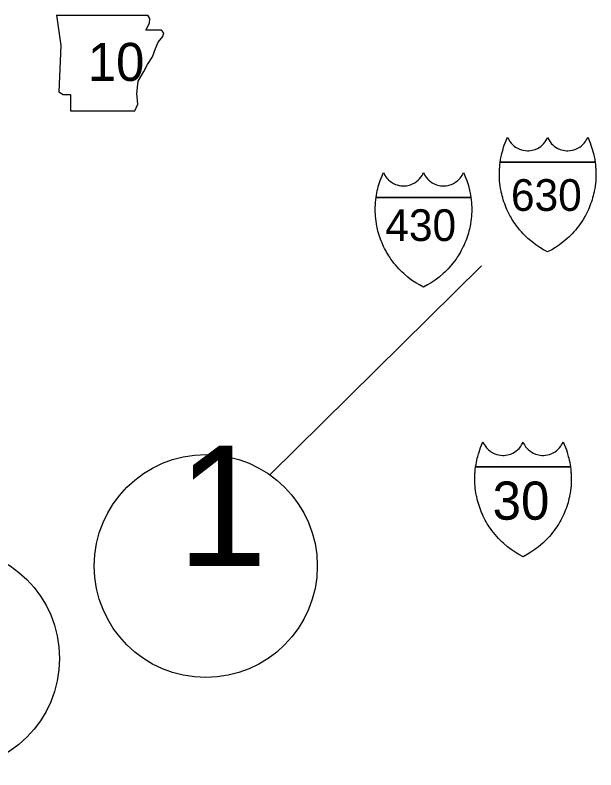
# Model space of a CAD drawing. Extents: x -819161 to 80911, y -6604 to 768454.
# Drawn here: x 43414 to 44380, y -5063 to -3807 of the extents above; entities that cross this region are included whole.
import ezdxf

# ---------------------------------------------------------------- set-up
doc = ezdxf.new("R2010")
doc.units = 0
for name, color, linetype in [('21', 7, 'Continuous'), ('23', 7, 'Continuous'), ('DSN_DRFT_Common-Line', 7, 'Continuous'), ('Level 23', 7, 'Continuous')]:
    doc.layers.add(name, color=color, linetype=linetype)

msp = doc.modelspace()

# ---------------------------------------------------------------- linework, layer by layer
at = {"layer": '21'}
for p, q in [((43482.9, -3807.3), (43490.5, -3858)), ((43638.5, -3813.2), (43635, -3807.3)), ((43637.7, -3820.8), (43638.5, -3813.2)), ((43631.8, -3832.6), (43637.7, -3820.8)), ((43658, -3832.6), (43631.8, -3832.6)), ((43661.4, -3836.9), (43658, -3832.6)), ((43659.7, -3842.8), (43661.4, -3836.9)), ((43647.9, -3863.1), (43652.1, -3852.1)), ((43652.1, -3852.1), (43659.7, -3842.8)), ((43490.5, -3858), (43487.1, -3935)), ((43642.8, -3876.6), (43647.9, -3863.1)), ((43634.3, -3889.3), (43642.8, -3876.6)), ((43628.4, -3901.2), (43634.3, -3889.3)), ((43619.1, -3917.2), (43628.4, -3901.2)), ((43616.6, -3937.5), (43619.1, -3917.2)), ((43487.1, -3935), (43493.9, -3939.2)), ((43493.9, -3939.2), (43506.6, -3939.2)), ((43506.6, -3939.2), (43506.6, -3966.3)), ((43618.2, -3955.3), (43616.6, -3937.5)), ((43613.2, -3966.3), (43618.2, -3955.3)), ((43506.6, -3966.3), (43613.2, -3966.3))]:
    msp.add_line(p, q, dxfattribs=at)
msp.add_lwpolyline([(43482.9, -3807.3), (43635, -3807.3)], dxfattribs=at)
at = {"layer": '23'}
for points in [[(44221.3, -4051.9), (44221.9, -4048.2), (44222.5, -4044.8), (44223.4, -4040.5), (44224, -4037.7), (44224.9, -4034.4), (44226, -4030.5), (44227, -4027.2), (44228.1, -4023.9), (44229.6, -4019.7), (44231.2, -4015.8), (44232.5, -4012.8), (44233.5, -4010.5), (44234.7, -4013), (44236, -4015.5), (44237.5, -4017.7), (44239.4, -4020.2), (44240.9, -4021.9), (44242.8, -4023.7), (44244.7, -4025.3), (44246.8, -4026.8), (44250, -4028.7), (44253.4, -4030.3), (44256.4, -4031.4), (44259.4, -4032.1), (44262.7, -4032.7), (44266.4, -4032.9), (44268.9, -4032.9), (44271.7, -4032.6), (44274.2, -4032.2), (44276.9, -4031.5), (44279.6, -4030.6), (44283.3, -4029), (44285.8, -4027.6), (44288.7, -4025.6), (44291.5, -4023.2), (44293.5, -4021.2), (44295.9, -4018.3), (44297.8, -4015.4), (44298.9, -4013.4), (44300.2, -4010.8)], [(44300.2, -4010.8), (44301.4, -4013.4), (44302.6, -4015.4), (44304.5, -4018.3), (44306.8, -4021.2), (44308.9, -4023.2), (44311.7, -4025.6), (44314.6, -4027.6), (44317.1, -4029), (44320.8, -4030.6), (44323.5, -4031.5), (44326.2, -4032.2), (44328.7, -4032.6), (44331.5, -4032.9), (44334, -4032.9), (44337.7, -4032.7), (44340.9, -4032.1), (44343.9, -4031.4), (44347, -4030.3), (44350.3, -4028.7), (44353.6, -4026.8), (44355.7, -4025.3), (44357.6, -4023.7), (44359.4, -4021.9), (44360.9, -4020.2), (44362.9, -4017.7), (44364.3, -4015.5), (44365.7, -4013), (44366.8, -4010.5), (44367.9, -4012.8), (44369.2, -4015.8), (44370.7, -4019.7), (44372.3, -4023.9), (44373.4, -4027.2), (44374.4, -4030.5), (44375.5, -4034.4), (44376.3, -4037.7), (44377, -4040.5), (44377.9, -4044.8), (44378.5, -4048.2), (44379, -4051.9)], [(44300.2, -4201.3), (44293.3, -4197.6), (44287.2, -4194), (44280.5, -4189.5), (44274.3, -4184.7), (44267.4, -4178.9), (44264.9, -4176.5), (44262, -4173.7), (44259.3, -4170.9), (44256.4, -4167.7), (44253.5, -4164.4), (44251.1, -4161.4), (44248.5, -4158), (44246.1, -4154.7), (44244.1, -4151.7), (44242.2, -4148.9), (44240.8, -4146.5), (44238.8, -4143.1), (44237.2, -4140.4), (44235.6, -4137.2), (44233.9, -4133.8), (44232.5, -4130.7), (44231.2, -4127.8), (44229.8, -4124.4), (44228.7, -4121.3), (44227.5, -4118.1), (44226.4, -4114.7), (44225.4, -4111.3), (44224.5, -4108), (44223.7, -4104.8), (44223.1, -4102), (44222.6, -4100), (44221.9, -4096), (44221.1, -4091.3), (44220.7, -4087.5), (44220.3, -4083.4), (44220.1, -4080.1), (44219.9, -4075.9), (44219.9, -4072), (44220, -4067.7), (44220.1, -4064.8), (44220.3, -4062.2), (44220.4, -4060.6), (44220.8, -4056.3), (44221.3, -4051.9)], [(44379, -4051.9), (44221.3, -4051.9)], [(44221.3, -4051.9), (44379, -4051.9)], [(44379, -4051.9), (44379.6, -4056.3), (44380, -4060.6), (44380.1, -4062.2), (44380.3, -4064.8), (44380.4, -4067.7), (44380.5, -4072), (44380.4, -4075.9), (44380.3, -4080.1), (44380.1, -4083.4), (44379.7, -4087.5), (44379.2, -4091.3), (44378.5, -4096), (44377.7, -4100), (44377.3, -4102), (44376.7, -4104.8), (44375.9, -4108), (44375, -4111.3), (44374, -4114.7), (44372.9, -4118.1), (44371.7, -4121.3), (44370.5, -4124.4), (44369.2, -4127.8), (44367.9, -4130.7), (44366.4, -4133.8), (44364.8, -4137.2), (44363.1, -4140.4), (44361.6, -4143.1), (44359.6, -4146.5), (44358.1, -4148.9), (44356.3, -4151.7), (44354.3, -4154.7), (44351.9, -4158), (44349.3, -4161.4), (44346.9, -4164.4), (44344, -4167.7), (44341.1, -4170.9), (44338.4, -4173.7), (44335.5, -4176.5), (44332.9, -4178.9), (44326.1, -4184.7), (44319.9, -4189.5), (44313.2, -4194), (44307.1, -4197.6), (44300.2, -4201.3)], [(44014.8, -4110.5), (44015.3, -4106.7), (44015.9, -4103.4), (44016.8, -4099.1), (44017.5, -4096.3), (44018.3, -4092.9), (44019.4, -4089), (44020.4, -4085.8), (44021.5, -4082.4), (44023, -4078.3), (44024.6, -4074.4), (44025.9, -4071.4), (44027, -4069), (44028.1, -4071.6), (44029.5, -4074), (44030.9, -4076.2), (44032.8, -4078.7), (44034.4, -4080.4), (44036.2, -4082.2), (44038.1, -4083.8), (44040.2, -4085.3), (44043.5, -4087.3), (44046.8, -4088.8), (44049.9, -4089.9), (44052.9, -4090.7), (44056.1, -4091.2), (44059.8, -4091.5), (44062.3, -4091.4), (44065.1, -4091.1), (44067.6, -4090.7), (44070.3, -4090), (44073, -4089.1), (44076.7, -4087.5), (44079.2, -4086.1), (44082.1, -4084.1), (44084.9, -4081.8), (44087, -4079.7), (44089.3, -4076.9), (44091.2, -4074), (44092.4, -4072), (44093.6, -4069.3)], [(44093.6, -4069.3), (44094.9, -4072), (44096, -4074), (44097.9, -4076.9), (44100.2, -4079.7), (44102.3, -4081.8), (44105.1, -4084.1), (44108, -4086.1), (44110.5, -4087.5), (44114.2, -4089.1), (44116.9, -4090), (44119.6, -4090.7), (44122.1, -4091.1), (44124.9, -4091.4), (44127.4, -4091.5), (44131.1, -4091.2), (44134.4, -4090.7), (44137.4, -4089.9), (44140.4, -4088.8), (44143.8, -4087.3), (44147, -4085.3), (44149.1, -4083.8), (44151, -4082.2), (44152.9, -4080.4), (44154.4, -4078.7), (44156.3, -4076.2), (44157.8, -4074), (44159.1, -4071.6), (44160.3, -4069), (44161.3, -4071.4), (44162.6, -4074.4), (44164.2, -4078.3), (44165.7, -4082.4), (44166.8, -4085.8), (44167.8, -4089), (44168.9, -4092.9), (44169.8, -4096.3), (44170.4, -4099.1), (44171.3, -4103.4), (44171.9, -4106.7), (44172.5, -4110.5)], [(44093.6, -4259.9), (44086.7, -4256.2), (44080.6, -4252.5), (44073.9, -4248), (44067.7, -4243.3), (44060.9, -4237.4), (44058.3, -4235.1), (44055.4, -4232.2), (44052.7, -4229.5), (44049.8, -4226.3), (44046.9, -4222.9), (44044.5, -4219.9), (44041.9, -4216.5), (44039.5, -4213.3), (44037.5, -4210.2), (44035.7, -4207.5), (44034.2, -4205.1), (44032.2, -4201.7), (44030.7, -4198.9), (44029, -4195.7), (44027.3, -4192.4), (44025.9, -4189.3), (44024.6, -4186.3), (44023.3, -4183), (44022.1, -4179.9), (44020.9, -4176.6), (44019.8, -4173.3), (44018.8, -4169.8), (44017.9, -4166.5), (44017.1, -4163.4), (44016.5, -4160.6), (44016, -4158.5), (44015.3, -4154.5), (44014.6, -4149.9), (44014.1, -4146), (44013.7, -4141.9), (44013.5, -4138.6), (44013.4, -4134.5), (44013.3, -4130.6), (44013.4, -4126.2), (44013.5, -4123.4), (44013.7, -4120.7), (44013.8, -4119.1), (44014.2, -4114.8), (44014.8, -4110.5)], [(44172.5, -4110.5), (44014.8, -4110.5)], [(44014.8, -4110.5), (44172.5, -4110.5)], [(44172.5, -4110.5), (44173, -4114.8), (44173.4, -4119.1), (44173.5, -4120.7), (44173.7, -4123.4), (44173.8, -4126.2), (44173.9, -4130.6), (44173.9, -4134.5), (44173.7, -4138.6), (44173.5, -4141.9), (44173.1, -4146), (44172.6, -4149.9), (44171.9, -4154.5), (44171.2, -4158.5), (44170.7, -4160.6), (44170.1, -4163.4), (44169.3, -4166.5), (44168.4, -4169.8), (44167.4, -4173.3), (44166.3, -4176.6), (44165.1, -4179.9), (44164, -4183), (44162.6, -4186.3), (44161.3, -4189.3), (44159.9, -4192.4), (44158.2, -4195.7), (44156.5, -4198.9), (44155, -4201.7), (44153, -4205.1), (44151.5, -4207.5), (44149.7, -4210.2), (44147.7, -4213.3), (44145.3, -4216.5), (44142.7, -4219.9), (44140.3, -4222.9), (44137.4, -4226.3), (44134.5, -4229.5), (44131.8, -4232.2), (44128.9, -4235.1), (44126.4, -4237.4), (44119.5, -4243.3), (44113.3, -4248), (44106.6, -4252.5), (44100.5, -4256.2), (44093.6, -4259.9)], [(44180.4, -4558.8), (44181, -4555), (44181.6, -4551.7), (44182.4, -4547.4), (44183.1, -4544.6), (44183.9, -4541.3), (44185, -4537.3), (44186, -4534.1), (44187.2, -4530.7), (44188.7, -4526.6), (44190.2, -4522.7), (44191.5, -4519.7), (44192.6, -4517.3), (44193.7, -4519.9), (44195.1, -4522.3), (44196.6, -4524.5), (44198.5, -4527), (44200, -4528.7), (44201.9, -4530.5), (44203.8, -4532.1), (44205.8, -4533.6), (44209.1, -4535.6), (44212.5, -4537.1), (44215.5, -4538.2), (44218.5, -4539), (44221.7, -4539.5), (44225.5, -4539.8), (44227.9, -4539.7), (44230.7, -4539.4), (44233.3, -4539), (44236, -4538.4), (44238.7, -4537.5), (44242.3, -4535.8), (44244.8, -4534.4), (44247.8, -4532.4), (44250.6, -4530.1), (44252.6, -4528), (44254.9, -4525.2), (44256.9, -4522.3), (44258, -4520.3), (44259.2, -4517.6)], [(44259.2, -4517.6), (44260.5, -4520.3), (44261.6, -4522.3), (44263.5, -4525.2), (44265.9, -4528), (44267.9, -4530.1), (44270.7, -4532.4), (44273.7, -4534.4), (44276.2, -4535.8), (44279.8, -4537.5), (44282.5, -4538.4), (44285.2, -4539), (44287.7, -4539.4), (44290.6, -4539.7), (44293, -4539.8), (44296.8, -4539.5), (44300, -4539), (44303, -4538.2), (44306, -4537.1), (44309.4, -4535.6), (44312.7, -4533.6), (44314.7, -4532.1), (44316.6, -4530.5), (44318.5, -4528.7), (44320, -4527), (44321.9, -4524.5), (44323.4, -4522.3), (44324.7, -4519.9), (44325.9, -4517.3), (44327, -4519.7), (44328.3, -4522.7), (44329.8, -4526.6), (44331.3, -4530.7), (44332.4, -4534.1), (44333.4, -4537.3), (44334.5, -4541.3), (44335.4, -4544.6), (44336, -4547.4), (44336.9, -4551.7), (44337.5, -4555), (44338.1, -4558.8)], [(44259.2, -4708.2), (44252.3, -4704.5), (44246.3, -4700.8), (44239.6, -4696.3), (44233.3, -4691.6), (44226.5, -4685.8), (44224, -4683.4), (44221.1, -4680.6), (44218.4, -4677.8), (44215.4, -4674.6), (44212.6, -4671.2), (44210.1, -4668.2), (44207.5, -4664.8), (44205.2, -4661.6), (44203.1, -4658.5), (44201.3, -4655.8), (44199.8, -4653.4), (44197.8, -4650), (44196.3, -4647.2), (44194.6, -4644), (44193, -4640.7), (44191.6, -4637.6), (44190.3, -4634.6), (44188.9, -4631.3), (44187.7, -4628.2), (44186.6, -4625), (44185.5, -4621.6), (44184.4, -4618.1), (44183.5, -4614.8), (44182.7, -4611.7), (44182.1, -4608.9), (44181.7, -4606.8), (44180.9, -4602.8), (44180.2, -4598.2), (44179.7, -4594.3), (44179.4, -4590.2), (44179.2, -4586.9), (44179, -4582.8), (44179, -4578.9), (44179, -4574.5), (44179.2, -4571.7), (44179.3, -4569.1), (44179.4, -4567.4), (44179.8, -4563.1), (44180.4, -4558.8)], [(44338.1, -4558.8), (44180.4, -4558.8)], [(44180.4, -4558.8), (44338.1, -4558.8)], [(44338.1, -4558.8), (44338.6, -4563.1), (44339, -4567.4), (44339.2, -4569.1), (44339.3, -4571.7), (44339.4, -4574.5), (44339.5, -4578.9), (44339.5, -4582.8), (44339.3, -4586.9), (44339.1, -4590.2), (44338.8, -4594.3), (44338.3, -4598.2), (44337.6, -4602.8), (44336.8, -4606.8), (44336.4, -4608.9), (44335.7, -4611.7), (44335, -4614.8), (44334.1, -4618.1), (44333, -4621.6), (44331.9, -4625), (44330.8, -4628.2), (44329.6, -4631.3), (44328.2, -4634.6), (44326.9, -4637.6), (44325.5, -4640.7), (44323.9, -4644), (44322.2, -4647.2), (44320.6, -4650), (44318.7, -4653.4), (44317.2, -4655.8), (44315.4, -4658.5), (44313.3, -4661.6), (44310.9, -4664.8), (44308.3, -4668.2), (44305.9, -4671.2), (44303.1, -4674.6), (44300.1, -4677.8), (44297.4, -4680.6), (44294.5, -4683.4), (44292, -4685.8), (44285.2, -4691.6), (44278.9, -4696.3), (44272.2, -4700.8), (44266.2, -4704.5), (44259.2, -4708.2)]]:
    msp.add_lwpolyline(points, dxfattribs=at)
at = {"layer": 'DSN_DRFT_Common-Line'}
msp.add_lwpolyline([(43838.1, -4572), (44190, -4224.6)], dxfattribs=at)
for centre in [(43731.4, -4723.8), (43302.5, -4877.4)]:
    msp.add_circle(centre, 185.5, dxfattribs=at)

# ---------------------------------------------------------------- texts
at = {"layer": '21'}
msp.add_text('10', height=63.36, dxfattribs=at).set_placement((43535, -3916.8))
at = {"layer": 'DSN_DRFT_Common-Line'}
msp.add_text('1', height=200.4, dxfattribs=at).set_placement((43684.4, -4723.8))
at = {"layer": 'Level 23'}
for s, height, p in [('630', 52.8, (44239.1, -4133)), ('430', 52.8, (44030.1, -4183.1)), ('30', 63.52, (44208.6, -4646.7))]:
    msp.add_text(s, height=height, dxfattribs=at).set_placement(p)

doc.saveas('drawing.dxf')
